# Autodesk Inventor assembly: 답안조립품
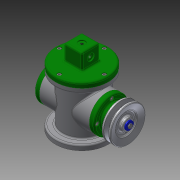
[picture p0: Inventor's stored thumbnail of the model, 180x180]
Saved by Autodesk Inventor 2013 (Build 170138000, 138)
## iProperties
Created: 2018-02
Part Number: 답안조립품
Document SubType Name: Assembly
Designer: Administrator
Author: Administrator
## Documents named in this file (18)
- C:\Users\Administrator\Desktop\480208V1012\답안조립품.iam
- C:\Users\Administrator\Desktop\480208V1012\본체.ipt
- C:\Users\Administrator\Desktop\480208V1012\E-링.ipt
- C:\Users\Administrator\Desktop\480208V1012\V-벨트풀리.ipt
- C:\Users\Administrator\Desktop\480208V1012\덮개.ipt
- C:\Users\Administrator\Desktop\480208V1012\뒤커버.ipt
- C:\Users\Administrator\Desktop\480208V1012\링크.ipt
- C:\Users\Administrator\Desktop\480208V1012\베어링 17 x 40 x 12.ipt
- C:\Users\Administrator\Desktop\480208V1012\볼트 M4 x 8.ipt
- C:\Users\Administrator\Desktop\480208V1012\볼트 M4 x 10.ipt
- C:\Users\Administrator\Desktop\480208V1012\슬라이더.ipt
- C:\Users\Administrator\Desktop\480208V1012\앞커버.ipt
- C:\Users\Administrator\Desktop\480208V1012\오일 실 17 30 8.ipt
- C:\Users\Administrator\Desktop\480208V1012\와셔 4x16.ipt
- C:\Users\Administrator\Desktop\480208V1012\클레비스 핀 6 x 22.ipt
- 클레비스 핀 6 x 22.ipt
- C:\Users\Administrator\Desktop\480208V1012\키 4 x 4 x 12.ipt
- C:\Users\Administrator\Desktop\480208V1012\편심축.ipt
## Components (2 placed, 2 different names)
1. E-링:1
2. V-벨트풀리:1
